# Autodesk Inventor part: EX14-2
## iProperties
Author: J. DESIGNER
Revision Number: A
Created: 2001-10
Part Number: EX14-2
Description: STRUT, SCOOTER
Document SubType Name: Modeling
Designer: J. DESIGNER
Control State: 0
Master: False
Checked Out: False
PropertySet Name: Design Tracking Control
Shininess: 88.0
Angle Display Precision: 2
Document Length Units: 11272
Document Angle Units: 11286
Document Time Units: 11279
Document Mass Units: 11290
Document Length Units Precision: 3
Document Angle Units Precision: 2
Compacted: False
PropertySet Name: _Private Model Information
Density: 0.0
Volumn: 0.0
Area: 0.0
PropertySet Name: Model Information
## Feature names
1. Extrusion1
2. Sweep1
3. Extrusion2
4. Loft1
5. Mirror1
6. Hole1
